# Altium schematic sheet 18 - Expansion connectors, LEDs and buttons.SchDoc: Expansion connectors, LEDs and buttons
size A3; PageSetup: Record=PageOptions¦CenterHorizontal=True¦CenterVertical=True¦PrintScale=0.70¦XCorrection=1.00¦YCorrection=1.00¦PrintKind=0¦BorderSize=5000000¦LeftOffset=0¦BottomOffset=0¦Orientation=2¦PaperLength=4200¦PaperWidth=2970¦Scale=100¦PaperSource=7¦PrintQuality=600¦MediaType=1¦DitherType=10¦PaperKind=A4¦PrintScaleMode=1; Author: Juan Anzola; SheetNumber: 18; SheetTotal: 20
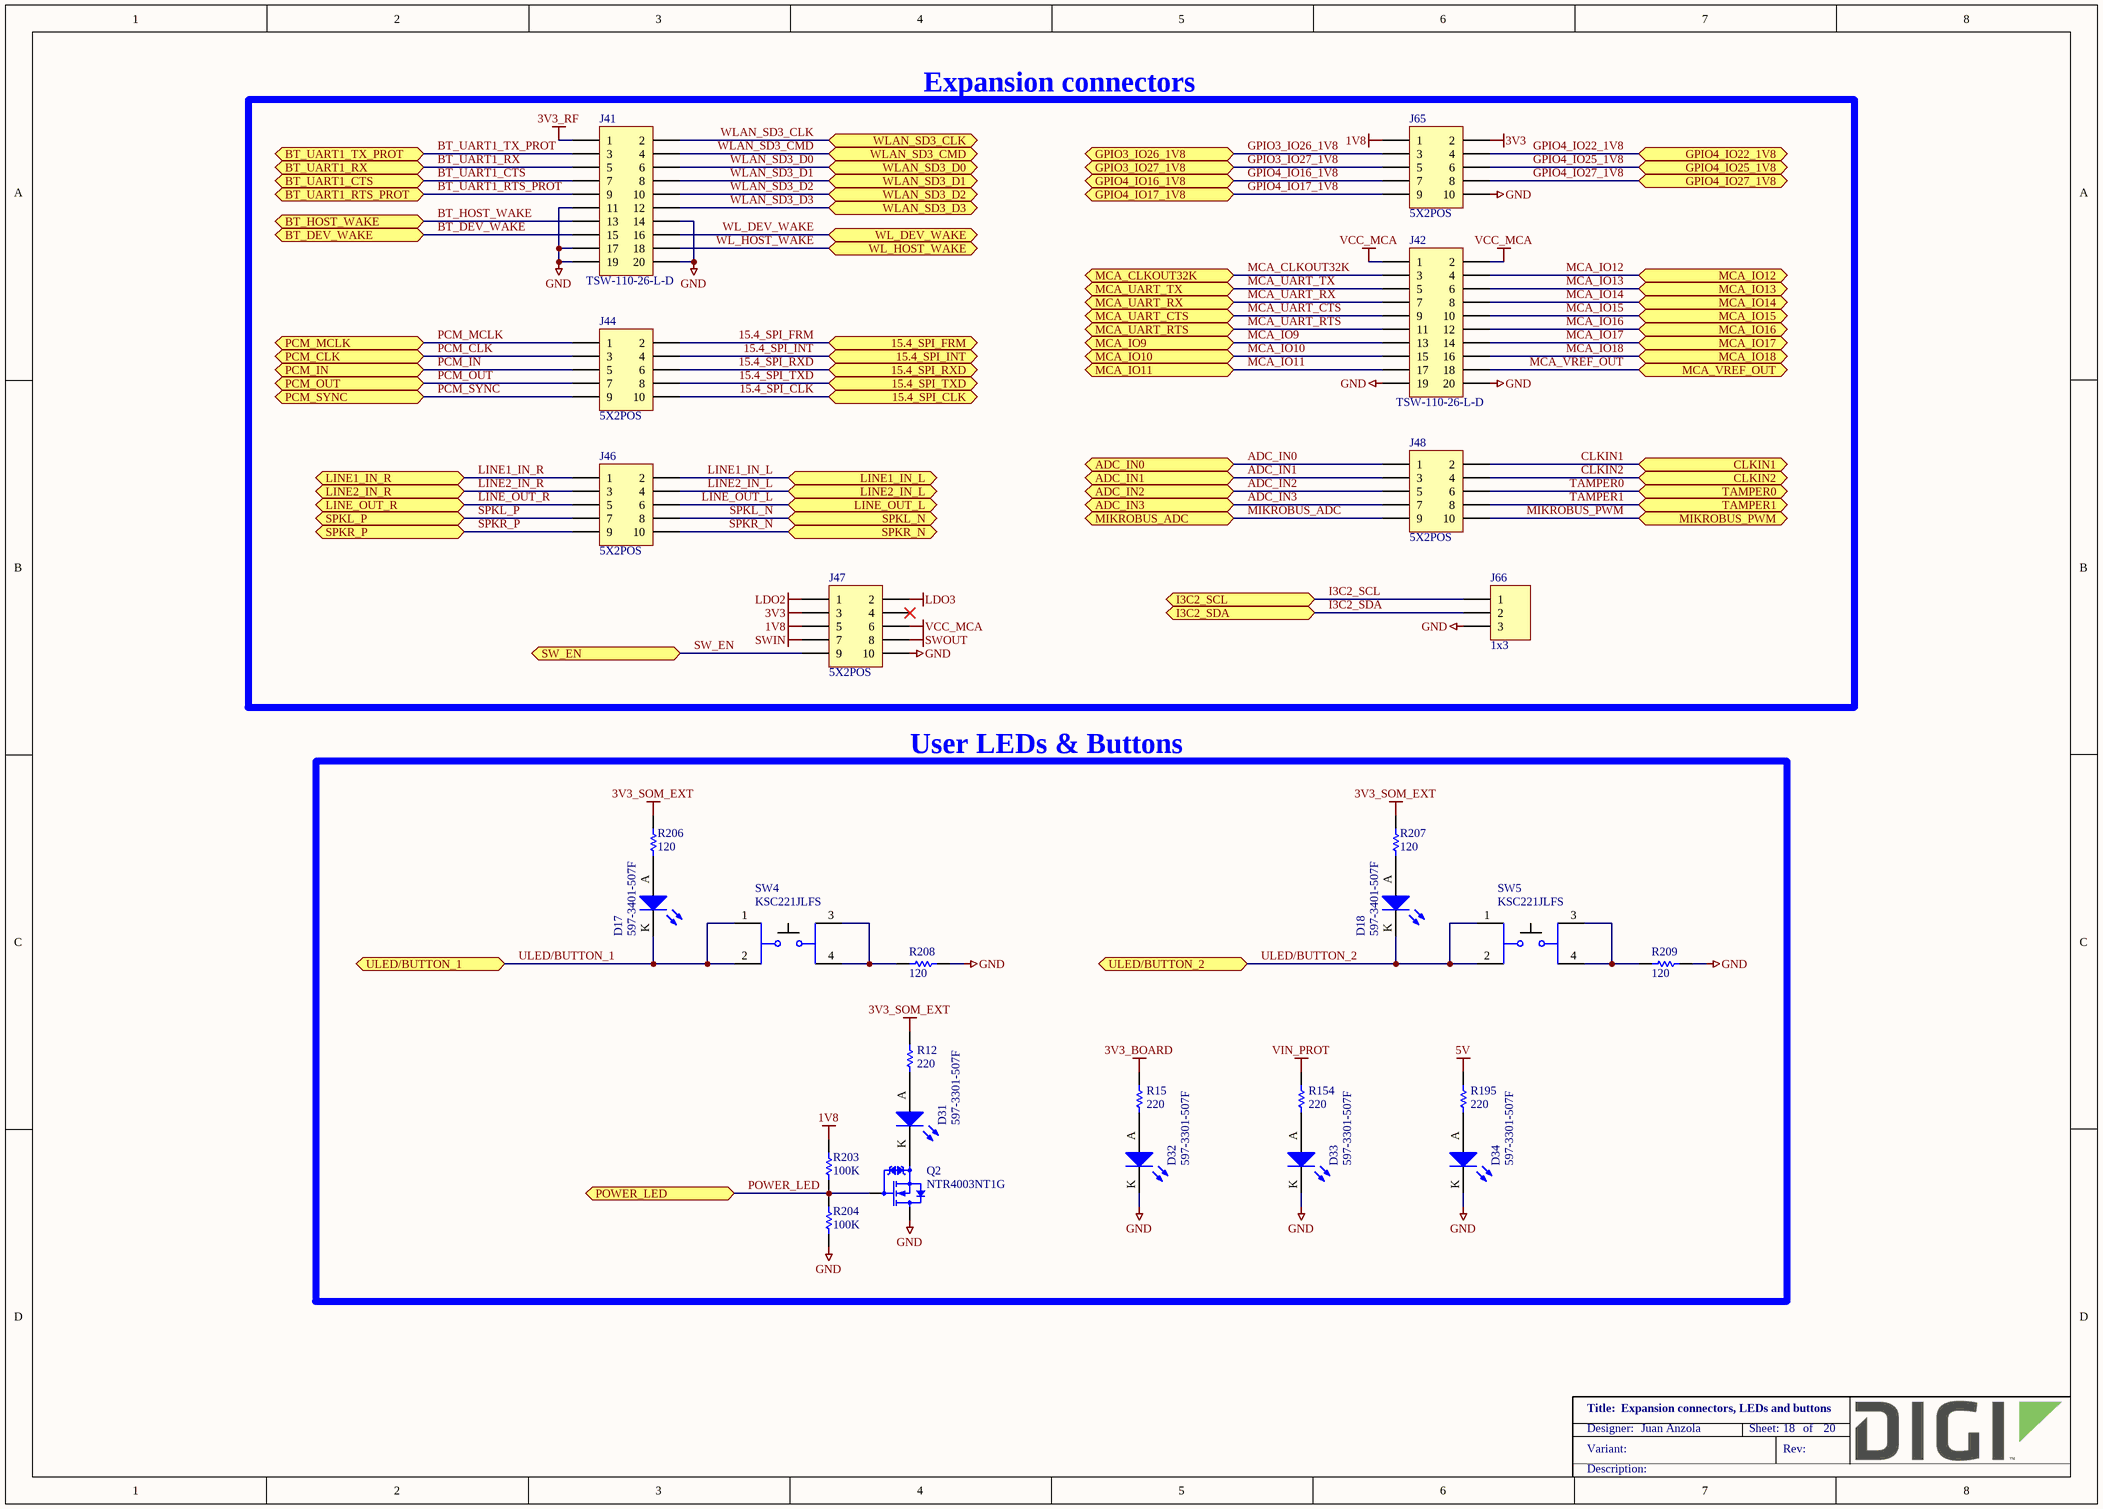
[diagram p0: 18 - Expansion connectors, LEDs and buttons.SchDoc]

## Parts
D17  597-3401-507F  [LEDM3020X130N_YELLOW]
D18  597-3401-507F  [LEDM3020X130N_YELLOW]
D31  597-3301-507F  [LEDM3020X130N]
D32  597-3301-507F  [LEDM3020X130N]
D33  597-3301-507F  [LEDM3020X130N]
D34  597-3301-507F  [LEDM3020X130N]
J41  TSW-110-26-L-D  [SAMTEC_TSW-110-26-L-D]
J42  TSW-110-26-L-D  [SAMTEC_TSW-110-26-L-D]
J44  5X2POS  [MOLEX_87914-1016]
J46  5X2POS  [MOLEX_87914-1016]
J47  5X2POS  [MOLEX_87914-1016]
J48  5X2POS  [MOLEX_87914-1016]
J65  5X2POS  [MOLEX_87914-1016]
J66  1x3  [SAMTEC_TSW-103-07-G-S]
Q2  NTR4003NT1G  [SOT95P240X110_GSD-3N]
R12  220  [RESC1005X40N]
R15  220  [RESC1005X40N]
R154  220  [RESC1005X40N]
R195  220  [RESC1005X40N]
R203  100K  [RESC1005X40N]
R204  100K  [RESC1005X40N]
R206  120  [RESC1005X40N]
R207  120  [RESC1005X40N]
R208  120  [RESC1005X40N]
R209  120  [RESC1005X40N]
SW4  KSC221JLFS  [SW_KSC221J]
SW5  KSC221JLFS  [SW_KSC221J]

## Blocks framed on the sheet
Expansion connectors: J41 J42 J44 J46-J48 J65 J66
User LEDs & Buttons: D17 D18 D31-D34 Q2 R12 R15 R154 R195 R203 R204 R206-R209 SW4 SW5

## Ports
15.4_SPI_CLK (bidir), 15.4_SPI_FRM (bidir), 15.4_SPI_INT (bidir), 15.4_SPI_RXD (bidir), 15.4_SPI_TXD (bidir), ADC_IN0 (bidir), ADC_IN1 (bidir), ADC_IN2 (bidir), ADC_IN3 (bidir), BT_DEV_WAKE (bidir), BT_HOST_WAKE (bidir), BT_UART1_CTS (bidir), BT_UART1_RTS_PROT (bidir), BT_UART1_RX (bidir), BT_UART1_TX_PROT (bidir), CLKIN1 (bidir), CLKIN2 (bidir), GPIO3_IO26_1V8 (bidir), GPIO3_IO27_1V8 (bidir), GPIO4_IO16_1V8 (bidir), GPIO4_IO17_1V8 (bidir), GPIO4_IO22_1V8 (bidir), GPIO4_IO25_1V8 (bidir), GPIO4_IO27_1V8 (bidir), I3C2_SCL (bidir), I3C2_SDA (bidir), LINE1_IN_L (bidir), LINE1_IN_R (bidir), LINE2_IN_L (bidir), LINE2_IN_R (bidir), LINE_OUT_L (bidir), LINE_OUT_R (bidir), MCA_CLKOUT32K (bidir), MCA_IO9 (bidir), MCA_IO10 (bidir), MCA_IO11 (bidir), MCA_IO12 (bidir), MCA_IO13 (bidir), MCA_IO14 (bidir), MCA_IO15 (bidir), MCA_IO16 (bidir), MCA_IO17 (bidir), MCA_IO18 (bidir), MCA_UART_CTS (bidir), MCA_UART_RTS (bidir), MCA_UART_RX (bidir), MCA_UART_TX (bidir), MCA_VREF_OUT (bidir), MIKROBUS_ADC (bidir), MIKROBUS_PWM (bidir), PCM_CLK (bidir), PCM_IN (bidir), PCM_MCLK (bidir), PCM_OUT (bidir), PCM_SYNC (bidir), POWER_LED (bidir), SPKL_N (bidir), SPKL_P (bidir), SPKR_N (bidir), SPKR_P (bidir), SW_EN (bidir), TAMPER0 (bidir), TAMPER1 (bidir), ULED/BUTTON_1 (bidir), ULED/BUTTON_2 (bidir), WL_DEV_WAKE (bidir), WL_HOST_WAKE (bidir), WLAN_SD3_CLK (bidir), WLAN_SD3_CMD (bidir), WLAN_SD3_D0 (bidir), WLAN_SD3_D1 (bidir), WLAN_SD3_D2 (bidir), WLAN_SD3_D3 (bidir)

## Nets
1V8: J47.5 J65.1 R203.1
3V3: J47.3 J65.2
3V3_BOARD: R15.2
3V3_RF: J41.1
3V3_SOM_EXT: R12.2 R206.2 R207.2
5V: R195.2
GND: D32.K D33.K D34.K J41.11 J41.14 J41.17 J41.19 J41.20 J42.19 J42.20 J47.10 J65.10 J66.3 Q2.D R204.2 R208.1 R209.1
LDO2: J47.1
LDO3: J47.2
SWIN: J47.7
SWOUT: J47.8
VCC_MCA: J42.1 J42.2 J47.6
VIN_PROT: R154.2
15.4_SPI_CLK: J44.10 ; port 15.4_SPI_CLK
15.4_SPI_FRM: J44.2 ; port 15.4_SPI_FRM
15.4_SPI_INT: J44.4 ; port 15.4_SPI_INT
15.4_SPI_RXD: J44.6 ; port 15.4_SPI_RXD
15.4_SPI_TXD: J44.8 ; port 15.4_SPI_TXD
ADC_IN0: J48.1 ; port ADC_IN0
ADC_IN1: J48.3 ; port ADC_IN1
ADC_IN2: J48.5 ; port ADC_IN2
ADC_IN3: J48.7 ; port ADC_IN3
BT_DEV_WAKE: J41.15 ; port BT_DEV_WAKE
BT_HOST_WAKE: J41.13 ; port BT_HOST_WAKE
BT_UART1_CTS: J41.7 ; port BT_UART1_CTS
BT_UART1_RTS_PROT: J41.9 ; port BT_UART1_RTS_PROT
BT_UART1_RX: J41.5 ; port BT_UART1_RX
BT_UART1_TX_PROT: J41.3 ; port BT_UART1_TX_PROT
CLKIN1: J48.2 ; port CLKIN1
CLKIN2: J48.4 ; port CLKIN2
GPIO3_IO26_1V8: J65.3 ; port GPIO3_IO26_1V8
GPIO3_IO27_1V8: J65.5 ; port GPIO3_IO27_1V8
GPIO4_IO16_1V8: J65.7 ; port GPIO4_IO16_1V8
GPIO4_IO17_1V8: J65.9 ; port GPIO4_IO17_1V8
GPIO4_IO22_1V8: J65.4 ; port GPIO4_IO22_1V8
GPIO4_IO25_1V8: J65.6 ; port GPIO4_IO25_1V8
GPIO4_IO27_1V8: J65.8 ; port GPIO4_IO27_1V8
I3C2_SCL: J66.1 ; port I3C2_SCL
I3C2_SDA: J66.2 ; port I3C2_SDA
LINE1_IN_L: J46.2 ; port LINE1_IN_L
LINE1_IN_R: J46.1 ; port LINE1_IN_R
LINE2_IN_L: J46.4 ; port LINE2_IN_L
LINE2_IN_R: J46.3 ; port LINE2_IN_R
LINE_OUT_L: J46.6 ; port LINE_OUT_L
LINE_OUT_R: J46.5 ; port LINE_OUT_R
MCA_CLKOUT32K: J42.3 ; port MCA_CLKOUT32K
MCA_IO9: J42.13 ; port MCA_IO9
MCA_IO10: J42.15 ; port MCA_IO10
MCA_IO11: J42.17 ; port MCA_IO11
MCA_IO12: J42.4 ; port MCA_IO12
MCA_IO13: J42.6 ; port MCA_IO13
MCA_IO14: J42.8 ; port MCA_IO14
MCA_IO15: J42.10 ; port MCA_IO15
MCA_IO16: J42.12 ; port MCA_IO16
MCA_IO17: J42.14 ; port MCA_IO17
MCA_IO18: J42.16 ; port MCA_IO18
MCA_UART_CTS: J42.9 ; port MCA_UART_CTS
MCA_UART_RTS: J42.11 ; port MCA_UART_RTS
MCA_UART_RX: J42.7 ; port MCA_UART_RX
MCA_UART_TX: J42.5 ; port MCA_UART_TX
MCA_VREF_OUT: J42.18 ; port MCA_VREF_OUT
MIKROBUS_ADC: J48.9 ; port MIKROBUS_ADC
MIKROBUS_PWM: J48.10 ; port MIKROBUS_PWM
PCM_CLK: J44.3 ; port PCM_CLK
PCM_IN: J44.5 ; port PCM_IN
PCM_MCLK: J44.1 ; port PCM_MCLK
PCM_OUT: J44.7 ; port PCM_OUT
PCM_SYNC: J44.9 ; port PCM_SYNC
POWER_LED: Q2.G R203.2 R204.1 ; port POWER_LED
SPKL_N: J46.8 ; port SPKL_N
SPKL_P: J46.7 ; port SPKL_P
SPKR_N: J46.10 ; port SPKR_N
SPKR_P: J46.9 ; port SPKR_P
SW_EN: J47.9 ; port SW_EN
TAMPER0: J48.6 ; port TAMPER0
TAMPER1: J48.8 ; port TAMPER1
ULED/BUTTON_1: D17.K SW4.1 SW4.2 ; port ULED/BUTTON_1
ULED/BUTTON_2: D18.K SW5.1 SW5.2 ; port ULED/BUTTON_2
WL_DEV_WAKE: J41.16 ; port WL_DEV_WAKE
WL_HOST_WAKE: J41.18 ; port WL_HOST_WAKE
WLAN_SD3_CLK: J41.2 ; port WLAN_SD3_CLK
WLAN_SD3_CMD: J41.4 ; port WLAN_SD3_CMD
WLAN_SD3_D0: J41.6 ; port WLAN_SD3_D0
WLAN_SD3_D1: J41.8 ; port WLAN_SD3_D1
WLAN_SD3_D2: J41.10 ; port WLAN_SD3_D2
WLAN_SD3_D3: J41.12 ; port WLAN_SD3_D3
NetD17_A: D17.A R206.1
NetD18_A: D18.A R207.1
NetD31_A: D31.A R12.1
NetD31_K: D31.K Q2.S
NetD32_A: D32.A R15.1
NetD33_A: D33.A R154.1
NetD34_A: D34.A R195.1
NetR208_2: R208.2 SW4.3 SW4.4
NetR209_2: R209.2 SW5.3 SW5.4

Not connected (* = marked no-connect by the designer): J47 4*

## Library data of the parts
D17 D18 = 1001188: LED YELLOW 588NM 1208 SMD; Manufacturer: Dialight; Note: 17050842 = Digi No. for GE WDNU; Digi_PN: 17050387; Component_Life_Cycle_State: Reviewed; Area: 6
D31-D34 = 1001189: LED GREEN 573NM 1208 SMD; Manufacturer: Dialight; Digi_PN: 17050183; Component_Life_Cycle_State: Reviewed; Area: 6; Project: CCWMX6_SBC board; Note: 17050846 = Digi PN for GE WDNU II
J41 J42 = 1002751: CONN HEADER VERT 20POS 2.54MM; Part_Type: Connector; Manufacturer: Samtec; Digi_PN: 01730020; Component_Life_Cycle_State: Created; Area: 150,08
J44 J46-J48 J65 = 1001335: CONN HEADER 10POS DL VERT T/H; Part_Type: Connector; Manufacturer: Molex; Manufacturer_Part_Number: 87914-1016; Note: Check symbol pin-out upon reactivation; Digi_PN: 18000793; Component_Life_Cycle_State: Abandoned; Area: 63,5
J66 = 1002832: CONN HEADER 3POS .100" SGL GOLD; Part_Type: Connector; Manufacturer: Samtec; Manufacturer_Part_Number: TSW-103-07-G-S; Digi_PN: 00120003; Component_Life_Cycle_State: Pending; Area: 19,3548
Q2 = 1000306: MOSFET N-CH 30V 500MA SOT-23; Part_Type: Transistor; Manufacturer: On Semiconductor; Digi_PN: 17050809; Component_Life_Cycle_State: Proven; Area: 10,92
R12 R15 R154 R195 = 1001154: RES 220 OHM 1/16W 1% 0402 SMD; Part_Type: Resistor; Manufacturer: Yageo; Manufacturer_Part_Number: RC0402FR-07220RL; Digi_PN: 13050623; Component_Life_Cycle_State: Reviewed; Area: 0.95; Project: CCWMX6_SBC board
R203 R204 = 1000480: RES 100K OHM 1/10W 1% 0402 SMD; Part_Type: Resistor; Manufacturer: Panasonic - ECG; Manufacturer_Part_Number: ERJ-2RKF1003X; Digi_PN: 13051063; Component_Life_Cycle_State: CAD Reviewed; Area: 0.95; Project: KITT; Power_WV_SRF: 100
R206-R209 = 1001158: RES 120 OHM 1/16W 1% 0402 SMD; Part_Type: Resistor; Manufacturer: Yageo; Manufacturer_Part_Number: RC0402FR-07120RL; Note: 13051102 = Digi No. for GE WDNU; Digi_PN: 13050832; Component_Life_Cycle_State: Reviewed; Area: 0,95; Project: CCWMX6_SBC board
SW4 SW5 = 1001124: SWITCH TACTILE SPST-NO 0.05A 32V; Manufacturer: ITT; Digi_PN: 22000059; Component_Life_Cycle_State: Reviewed; Area: 37; Project: CCWMX6_SBC board; Note: 22000295 = Digi No. for GE WDNU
